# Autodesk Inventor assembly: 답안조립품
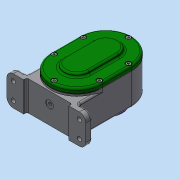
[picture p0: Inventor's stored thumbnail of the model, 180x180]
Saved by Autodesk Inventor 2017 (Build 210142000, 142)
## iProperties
Part Number: 답안조립품
Material: 일반
Document SubType Name: Assembly
Designer: MRC
Author: MRC
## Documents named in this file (19)
- C:\Users\MRC\Desktop\710609V1008\답안조립품.iam
- C:\Users\MRC\Desktop\710609V1008\본체.ipt
- C:\Users\MRC\Desktop\710609V1008\개스킷 A.ipt
- C:\Users\MRC\Desktop\710609V1008\개스킷 B.ipt
- C:\Users\MRC\Desktop\710609V1008\베어링 6001.ipt
- 베어링 6001.ipt
- C:\Users\MRC\Desktop\710609V1008\베어링 6002.ipt
- 베어링 6002.ipt
- C:\Users\MRC\Desktop\710609V1008\볼트 M4.ipt
- C:\Users\MRC\Desktop\710609V1008\스퍼기어 A.ipt
- C:\Users\MRC\Desktop\710609V1008\스퍼기어 B.ipt
- C:\Users\MRC\Desktop\710609V1008\오일 실 12 22 7.ipt
- C:\Users\MRC\Desktop\710609V1008\축 A.ipt
- C:\Users\MRC\Desktop\710609V1008\축 B.ipt
- C:\Users\MRC\Desktop\710609V1008\칼라.ipt
- C:\Users\MRC\Desktop\710609V1008\커버 A.ipt
- C:\Users\MRC\Desktop\710609V1008\커버 B.ipt
- C:\Users\MRC\Desktop\710609V1008\키 4 x 4 x 12.ipt
- C:\Users\MRC\Desktop\710609V1008\키 5 x 5 x 12.ipt
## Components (2 placed, 2 different names)
1. 개스킷 A:1
2. 개스킷 B:1
